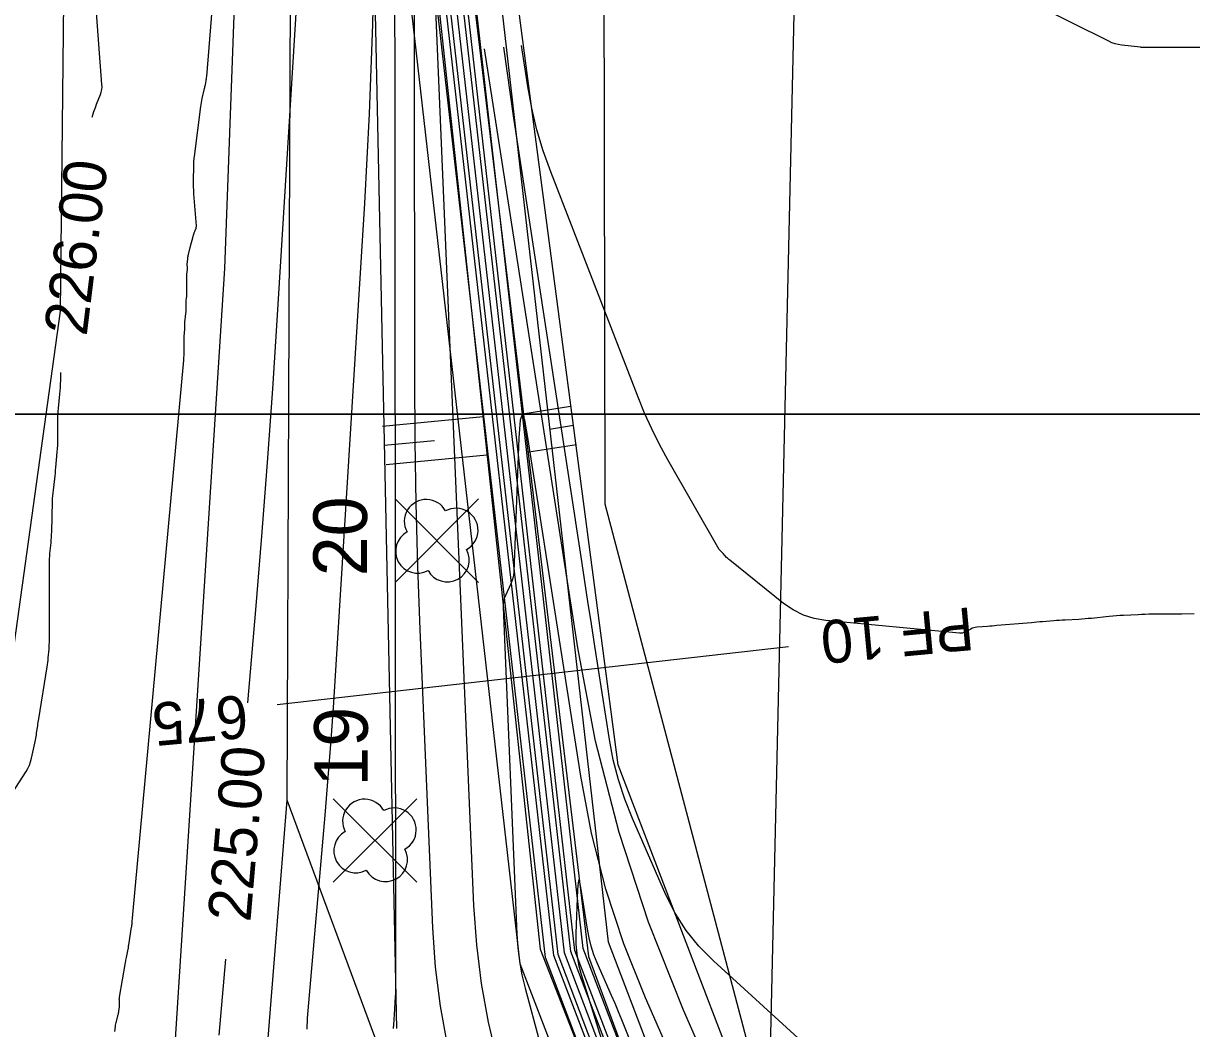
# Model space of a CAD drawing. Extents: x -534410 to -534262, y -1190162 to -1189584.
# Drawn here: x -534375.9 to -534348.66, y -1189913.8 to -1189890.36 of the extents above; entities that cross this region are included whole.
import ezdxf

# ---------------------------------------------------------------- set-up
doc = ezdxf.new("R2010")
doc.units = 0
for name, color, linetype in [('30', 7, 'Continuous'), ('31', 7, 'Continuous'), ('40', 7, 'Continuous'), ('_linie', 7, 'Continuous'), ('_N_osa', 7, 'Continuous'), ('_N_tenká', 7, 'Continuous'), ('_N_tenká_velmi', 7, 'Continuous'), ('_N_text', 7, 'Continuous'), ('_přístup', 7, 'Continuous'), ('_rámeček', 7, 'Continuous'), ('_tenka', 7, 'Continuous'), ('_velmi_tenka', 7, 'Continuous'), ('Default', 7, 'Continuous'), ('Hranice parcel', 7, 'Continuous')]:
    doc.layers.add(name, color=color, linetype=linetype)

msp = doc.modelspace()

# ---------------------------------------------------------------- linework, layer by layer
at = {"layer": '30'}
for points in [[(-534370.666, -1189906.203), (-534370.479, -1189904.035), (-534370.336, -1189902.317), (-534370.204, -1189900.599), (-534370.082, -1189898.88), (-534369.971, -1189897.16), (-534368.36, -1189871.02)], [(-534367.252, -1189877.424), (-534367.219, -1189912.738), (-534367.22, -1189912.819), (-534367.221, -1189912.899), (-534367.224, -1189912.979), (-534367.229, -1189913.06), (-534367.254, -1189913.474), (-534367.257, -1189913.507), (-534367.259, -1189913.541), (-534367.261, -1189913.575), (-534367.264, -1189913.609), (-534367.28, -1189913.791), (-534367.28, -1189913.8)], [(-534374.298, -1189892.543), (-534374.273, -1189892.468), (-534374.254, -1189892.41), (-534374.233, -1189892.353), (-534374.212, -1189892.296), (-534374.19, -1189892.24), (-534374.101, -1189892.014), (-534374.082, -1189891.956), (-534374.07, -1189891.898), (-534374.064, -1189891.839), (-534374.066, -1189891.779), (-534374.31, -1189888.535)], [(-534366.318, -1189889.293), (-534365.402, -1189910.932), (-534365.338, -1189911.844), (-534365.225, -1189912.749), (-534365.062, -1189913.646), (-534364.85, -1189914.535), (-534363.721, -1189918.76), (-534363.573, -1189919.304), (-534363.42, -1189919.847), (-534363.263, -1189920.389), (-534363.101, -1189920.929), (-534362.446, -1189923.087), (-534362.275, -1189923.625), (-534362.09, -1189924.157), (-534361.891, -1189924.684), (-534361.678, -1189925.205), (-534360.07, -1189929.007)], [(-534355.227, -1189925.422), (-534360.506, -1189913.368), (-534361.327, -1189911.316), (-534362.011, -1189909.224), (-534362.559, -1189907.092), (-534362.969, -1189904.92), (-534365.147, -1189890.948)], [(-534348.604, -1189904.127), (-534348.889, -1189904.131), (-534348.96, -1189904.132), (-534349.031, -1189904.132), (-534349.102, -1189904.133), (-534349.174, -1189904.134), (-534349.575, -1189904.136), (-534349.659, -1189904.137), (-534349.743, -1189904.139), (-534349.827, -1189904.142), (-534349.911, -1189904.146), (-534350.248, -1189904.163), (-534350.332, -1189904.168), (-534350.416, -1189904.174), (-534350.5, -1189904.181), (-534350.584, -1189904.189), (-534350.996, -1189904.231), (-534351.07, -1189904.238), (-534351.145, -1189904.245), (-534351.22, -1189904.25), (-534351.294, -1189904.255), (-534351.612, -1189904.273), (-534351.678, -1189904.276), (-534351.743, -1189904.281), (-534351.809, -1189904.285), (-534351.874, -1189904.29), (-534352.136, -1189904.311), (-534352.201, -1189904.316), (-534352.267, -1189904.321), (-534352.332, -1189904.326), (-534352.398, -1189904.332), (-534353.201, -1189904.401), (-534353.255, -1189904.406), (-534353.309, -1189904.41), (-534353.363, -1189904.415), (-534353.418, -1189904.419), (-534353.67, -1189904.439), (-534353.706, -1189904.444), (-534353.741, -1189904.452), (-534353.775, -1189904.464), (-534353.808, -1189904.48), (-534353.938, -1189904.549), (-534353.971, -1189904.564), (-534354.006, -1189904.574), (-534354.041, -1189904.578), (-534354.077, -1189904.577), (-534357.193, -1189904.28), (-534357.46, -1189904.235), (-534357.713, -1189904.154), (-534357.951, -1189904.036), (-534358.175, -1189903.882), (-534359.431, -1189902.875), (-534359.45, -1189902.859), (-534359.468, -1189902.843), (-534359.485, -1189902.826), (-534359.502, -1189902.809), (-534359.587, -1189902.718), (-534359.594, -1189902.711), (-534359.602, -1189902.703), (-534359.609, -1189902.696), (-534359.617, -1189902.688), (-534359.648, -1189902.659), (-534359.655, -1189902.652), (-534359.662, -1189902.644), (-534359.668, -1189902.635), (-534359.674, -1189902.626), (-534360.872, -1189900.532), (-534361.066, -1189900.177), (-534361.247, -1189899.815), (-534361.414, -1189899.447), (-534361.568, -1189899.072), (-534363.605, -1189893.818), (-534363.779, -1189893.331), (-534363.925, -1189892.836), (-534364.044, -1189892.335), (-534364.136, -1189891.826), (-534364.282, -1189890.875)], [(-534376.141, -1189908.282), (-534375.836, -1189907.806), (-534375.793, -1189907.732), (-534375.757, -1189907.655), (-534375.729, -1189907.575), (-534375.708, -1189907.493), (-534375.618, -1189907.069), (-534375.61, -1189907.028), (-534375.602, -1189906.987), (-534375.595, -1189906.945), (-534375.589, -1189906.904), (-534375.565, -1189906.737), (-534375.559, -1189906.696), (-534375.553, -1189906.654), (-534375.546, -1189906.613), (-534375.54, -1189906.571), (-534375.344, -1189905.363), (-534375.336, -1189905.311), (-534375.33, -1189905.26), (-534375.324, -1189905.208), (-534375.319, -1189905.156), (-534375.301, -1189904.948), (-534375.297, -1189904.896), (-534375.294, -1189904.844), (-534375.293, -1189904.792), (-534375.292, -1189904.74), (-534375.292, -1189902.971), (-534375.291, -1189902.908), (-534375.289, -1189902.845), (-534375.285, -1189902.782), (-534375.279, -1189902.719), (-534375.254, -1189902.468), (-534375.248, -1189902.405), (-534375.243, -1189902.342), (-534375.24, -1189902.279), (-534375.237, -1189902.216), (-534375.22, -1189901.504), (-534375.217, -1189901.438), (-534375.213, -1189901.372), (-534375.207, -1189901.306), (-534375.2, -1189901.24), (-534375.168, -1189900.976), (-534375.16, -1189900.91), (-534375.153, -1189900.844), (-534375.146, -1189900.778), (-534375.14, -1189900.712), (-534375.109, -1189900.359), (-534375.103, -1189900.277), (-534375.099, -1189900.196), (-534375.096, -1189900.115), (-534375.096, -1189900.034), (-534375.098, -1189899.651), (-534375.097, -1189899.57), (-534375.094, -1189899.489), (-534375.089, -1189899.408), (-534375.082, -1189899.328), (-534375.047, -1189899.006), (-534375.039, -1189898.925), (-534375.034, -1189898.844), (-534375.031, -1189898.763), (-534375.029, -1189898.683), (-534375.029, -1189898.498)], [(-534356.356, -1189927.44), (-534361.865, -1189913.788), (-534361.943, -1189913.596), (-534362.023, -1189913.405), (-534362.104, -1189913.215), (-534362.186, -1189913.025), (-534362.518, -1189912.267), (-534362.595, -1189912.075), (-534362.659, -1189911.88), (-534362.71, -1189911.681), (-534362.748, -1189911.478), (-534362.892, -1189910.553), (-534362.924, -1189910.387), (-534362.949, -1189910.332), (-534362.967, -1189910.389), (-534362.979, -1189910.558), (-534363.019, -1189911.581), (-534363.018, -1189911.825), (-534362.996, -1189912.067), (-534362.954, -1189912.305), (-534362.891, -1189912.541), (-534361.099, -1189918.283)], [(-534371.335, -1189913.953), (-534371.182, -1189912.181)]]:
    msp.add_lwpolyline(points, dxfattribs=at)
at = {"layer": '31'}
for points in [[(-534373.766, -1189913.868), (-534373.753, -1189913.749), (-534373.749, -1189913.719), (-534373.744, -1189913.69), (-534373.738, -1189913.66), (-534373.731, -1189913.631), (-534373.688, -1189913.472), (-534373.683, -1189913.451), (-534373.678, -1189913.431), (-534373.674, -1189913.41), (-534373.671, -1189913.388), (-534373.658, -1189913.3), (-534373.656, -1189913.281), (-534373.655, -1189913.261), (-534373.655, -1189913.242), (-534373.656, -1189913.223), (-534373.661, -1189913.145), (-534373.662, -1189913.125), (-534373.661, -1189913.106), (-534373.66, -1189913.086), (-534373.657, -1189913.067), (-534373.517, -1189912.257), (-534373.512, -1189912.229), (-534373.507, -1189912.2), (-534373.502, -1189912.172), (-534373.496, -1189912.144), (-534373.462, -1189911.982), (-534373.453, -1189911.94), (-534373.451, -1189911.928), (-534373.449, -1189911.916), (-534373.446, -1189911.881), (-534373.444, -1189911.865), (-534373.442, -1189911.849), (-534373.375, -1189911.434), (-534373.372, -1189911.417), (-534373.37, -1189911.4), (-534373.368, -1189911.383), (-534373.366, -1189911.365), (-534373.359, -1189911.279), (-534373.356, -1189911.244), (-534373.354, -1189911.227), (-534372.16, -1189898.211), (-534372.155, -1189898.153), (-534372.152, -1189898.096), (-534372.15, -1189898.038), (-534372.149, -1189897.98), (-534372.149, -1189897.663), (-534372.149, -1189897.649), (-534372.149, -1189897.634), (-534372.148, -1189897.62), (-534372.146, -1189897.605), (-534372.14, -1189897.547), (-534372.139, -1189897.533), (-534372.138, -1189897.518), (-534372.137, -1189897.504), (-534372.137, -1189897.489), (-534372.132, -1189897.325), (-534372.132, -1189897.31), (-534372.131, -1189897.294), (-534372.13, -1189897.279), (-534372.128, -1189897.264), (-534372.121, -1189897.203), (-534372.119, -1189897.188), (-534372.117, -1189897.173), (-534372.116, -1189897.157), (-534372.114, -1189897.142), (-534372.107, -1189897.061), (-534372.106, -1189897.042), (-534372.105, -1189897.023), (-534372.104, -1189897.004), (-534372.104, -1189896.986), (-534372.104, -1189896.897), (-534372.104, -1189896.879), (-534372.104, -1189896.86), (-534372.102, -1189896.841), (-534372.101, -1189896.823), (-534372.093, -1189896.748), (-534372.091, -1189896.73), (-534372.09, -1189896.711), (-534372.089, -1189896.692), (-534372.089, -1189896.674), (-534372.088, -1189896.562), (-534372.088, -1189896.513), (-534372.088, -1189896.432), (-534372.087, -1189896.383), (-534372.087, -1189896.291), (-534372.087, -1189896.27), (-534372.086, -1189896.25), (-534372.085, -1189896.229), (-534372.084, -1189896.208), (-534372.076, -1189896.097), (-534372.075, -1189896.083), (-534372.074, -1189896.07), (-534372.074, -1189896.056), (-534372.075, -1189896.043), (-534372.078, -1189895.989), (-534372.078, -1189895.976), (-534372.078, -1189895.963), (-534372.077, -1189895.949), (-534372.076, -1189895.936), (-534372.066, -1189895.832), (-534372.064, -1189895.81), (-534372.06, -1189895.788), (-534372.056, -1189895.767), (-534372.051, -1189895.746), (-534372.009, -1189895.585), (-534372.003, -1189895.563), (-534371.992, -1189895.519), (-534371.95, -1189895.356), (-534371.946, -1189895.341), (-534371.942, -1189895.327), (-534371.938, -1189895.312), (-534371.933, -1189895.298), (-534371.914, -1189895.24), (-534371.91, -1189895.226), (-534371.905, -1189895.213), (-534371.9, -1189895.2), (-534371.895, -1189895.187), (-534371.874, -1189895.135), (-534371.87, -1189895.122), (-534371.867, -1189895.108), (-534371.866, -1189895.095), (-534371.866, -1189895.081), (-534371.923, -1189894.332), (-534371.926, -1189894.282), (-534371.928, -1189894.233), (-534371.929, -1189894.183), (-534371.93, -1189894.133), (-534371.929, -1189893.908), (-534371.929, -1189893.87), (-534371.928, -1189893.833), (-534371.928, -1189893.796), (-534371.927, -1189893.758), (-534371.923, -1189893.608), (-534371.922, -1189893.571), (-534371.919, -1189893.534), (-534371.916, -1189893.496), (-534371.912, -1189893.459), (-534371.762, -1189892.294), (-534371.755, -1189892.247), (-534371.747, -1189892.2), (-534371.739, -1189892.154), (-534371.728, -1189892.108), (-534371.675, -1189891.878), (-534371.67, -1189891.854), (-534371.665, -1189891.831), (-534371.66, -1189891.808), (-534371.656, -1189891.785), (-534371.638, -1189891.692), (-534371.634, -1189891.669), (-534371.63, -1189891.645), (-534371.628, -1189891.622), (-534371.625, -1189891.598), (-534370.83, -1189881.739)], [(-534366.795, -1189883.114), (-534366.781, -1189898.62), (-534366.772, -1189900.088), (-534366.748, -1189901.556), (-534366.708, -1189903.024), (-534366.654, -1189904.491), (-534366.359, -1189911.452), (-534366.295, -1189912.368), (-534366.182, -1189913.277), (-534366.018, -1189914.179)], [(-534367.71, -1189888.284), (-534367.757, -1189890.373), (-534367.837, -1189892.462), (-534367.949, -1189894.549), (-534368.613, -1189905.317), (-534368.669, -1189906.194), (-534368.731, -1189907.07), (-534368.799, -1189907.946), (-534368.872, -1189908.822), (-534369.28, -1189913.554), (-534369.288, -1189913.812)], [(-534347.837, -1189890.92), (-534349.629, -1189890.921), (-534349.648, -1189890.921), (-534349.667, -1189890.921), (-534349.685, -1189890.92), (-534349.704, -1189890.92), (-534349.779, -1189890.918), (-534349.797, -1189890.918), (-534349.816, -1189890.916), (-534349.834, -1189890.915), (-534349.853, -1189890.913), (-534350.292, -1189890.863), (-534350.371, -1189890.85), (-534350.447, -1189890.831), (-534350.522, -1189890.806), (-534350.594, -1189890.773), (-534352.335, -1189889.91)], [(-534355.687, -1189915.981), (-534359.811, -1189912.222), (-534360.149, -1189911.88), (-534360.447, -1189911.509), (-534360.703, -1189911.109), (-534360.918, -1189910.679), (-534361.697, -1189908.901), (-534361.876, -1189908.452), (-534362.026, -1189907.994), (-534362.146, -1189907.528), (-534362.235, -1189907.053), (-534362.574, -1189904.883), (-534362.655, -1189904.362), (-534362.736, -1189903.84), (-534362.816, -1189903.318), (-534362.896, -1189902.797), (-534364.462, -1189892.567), (-534364.694, -1189890.91)], [(-534358.887, -1189918.812), (-534361.396, -1189913.081), (-534361.899, -1189911.826), (-534362.317, -1189910.547), (-534362.652, -1189909.243), (-534362.903, -1189907.914), (-534364.135, -1189900.011), (-534364.211, -1189899.607), (-534364.272, -1189899.474), (-534364.317, -1189899.613), (-534364.346, -1189900.023), (-534364.467, -1189903.148), (-534364.473, -1189903.221), (-534364.487, -1189903.293), (-534364.508, -1189903.362), (-534364.535, -1189903.43), (-534364.66, -1189903.699), (-534364.687, -1189903.767), (-534364.705, -1189903.837), (-534364.715, -1189903.909), (-534364.716, -1189903.982), (-534364.394, -1189911.593), (-534364.372, -1189911.913), (-534364.332, -1189912.23), (-534364.275, -1189912.545), (-534364.201, -1189912.857), (-534363.869, -1189914.099)]]:
    msp.add_lwpolyline(points, dxfattribs=at)
at = {"layer": '_linie'}
for points in [[(-534366.12, -1189620.81), (-534364.52, -1189627.2), (-534365.69, -1189653.8), (-534366.76, -1189684.81), (-534368.14, -1189748.73), (-534368.38, -1189779.14), (-534368.65, -1189820.64), (-534368.59, -1189847.58), (-534367.2, -1189913.8)], [(-534363.12, -1189621.02), (-534362.79, -1189621.58), (-534361.82, -1189627.79), (-534363.46, -1189653.55), (-534365.47, -1189684.77), (-534366.65, -1189748.83), (-534366.75, -1189779.47), (-534366.9, -1189820.47), (-534366.95, -1189846.72), (-534366.338, -1189888.804), (-534363.85, -1189911.95), (-534357.07, -1189929.19), (-534352.334, -1189940.856)], [(-534359.03, -1189621.26), (-534359.41, -1189621.83), (-534360.84, -1189627.76), (-534362.92, -1189653.56), (-534364.64, -1189685), (-534365.94, -1189748.9), (-534366.02, -1189779.52), (-534366.03, -1189820.5), (-534366.48, -1189846.73), (-534365.511, -1189888.873), (-534362.72, -1189912.12), (-534356.62, -1189928.64), (-534351.589, -1189940.594)]]:
    msp.add_lwpolyline(points, dxfattribs=at)
at = {"layer": '_N_osa'}
msp.add_lwpolyline([(-534351.95, -1189940.722), (-534356.845, -1189928.915), (-534363.285, -1189912.035), (-534365.925, -1189888.838), (-534366.715, -1189846.725), (-534366.465, -1189820.485), (-534366.385, -1189779.495), (-534366.295, -1189748.865), (-534365.055, -1189684.885), (-534363.19, -1189653.555), (-534361.333, -1189627.822)], dxfattribs=at)
at = {"layer": '_N_tenká'}
for points in [[(-534352.92, -1189941.124), (-534357.821, -1189929.303), (-534364.313, -1189912.285), (-534366.973, -1189888.908), (-534367.765, -1189846.73), (-534367.515, -1189820.479), (-534367.435, -1189779.492), (-534367.345, -1189748.853), (-534366.104, -1189684.844), (-534364.238, -1189653.486), (-534362.424, -1189628.352), (-534361.782, -1189627.792)], [(-534350.98, -1189940.319), (-534355.869, -1189928.527), (-534362.257, -1189911.785), (-534364.876, -1189888.769), (-534365.665, -1189846.72), (-534365.415, -1189820.491), (-534365.335, -1189779.498), (-534365.245, -1189748.877), (-534364.006, -1189684.926), (-534362.142, -1189653.624), (-534360.329, -1189628.488), (-534360.884, -1189627.851)]]:
    msp.add_lwpolyline(points, dxfattribs=at)
at = {"layer": '_N_tenká_velmi'}
for points in [[(-534352.366, -1189940.894), (-534357.263, -1189929.081), (-534363.726, -1189912.142), (-534366.374, -1189888.868), (-534367.165, -1189846.727), (-534366.915, -1189820.482), (-534366.835, -1189779.494), (-534366.745, -1189748.86), (-534365.505, -1189684.867), (-534363.639, -1189653.525), (-534361.782, -1189627.792)], [(-534352.181, -1189940.817), (-534357.077, -1189929.007), (-534363.53, -1189912.095), (-534366.174, -1189888.855), (-534366.965, -1189846.726), (-534366.715, -1189820.484), (-534366.635, -1189779.494), (-534366.545, -1189748.862), (-534365.305, -1189684.875), (-534363.439, -1189653.539), (-534361.583, -1189627.805)], [(-534352.089, -1189940.779), (-534356.984, -1189928.97), (-534363.432, -1189912.071), (-534366.074, -1189888.848), (-534366.865, -1189846.726), (-534366.615, -1189820.484), (-534366.535, -1189779.495), (-534366.445, -1189748.863), (-534365.205, -1189684.879), (-534363.34, -1189653.545), (-534361.483, -1189627.812)], [(-534351.812, -1189940.664), (-534356.706, -1189928.86), (-534363.138, -1189911.999), (-534365.775, -1189888.828), (-534366.565, -1189846.724), (-534366.315, -1189820.486), (-534366.235, -1189779.495), (-534366.145, -1189748.867), (-534364.905, -1189684.891), (-534363.04, -1189653.565), (-534361.184, -1189627.831)], [(-534351.719, -1189940.626), (-534356.613, -1189928.823), (-534363.04, -1189911.975), (-534365.675, -1189888.822), (-534366.465, -1189846.724), (-534366.215, -1189820.486), (-534366.135, -1189779.496), (-534366.045, -1189748.868), (-534364.805, -1189684.895), (-534362.941, -1189653.571), (-534361.084, -1189627.838)], [(-534351.534, -1189940.549), (-534356.427, -1189928.749), (-534362.844, -1189911.928), (-534365.475, -1189888.808), (-534366.265, -1189846.723), (-534366.015, -1189820.488), (-534365.935, -1189779.496), (-534365.845, -1189748.87), (-534364.605, -1189684.903), (-534362.741, -1189653.585), (-534360.884, -1189627.851)]]:
    msp.add_lwpolyline(points, dxfattribs=at)
at = {"layer": '_N_text'}
msp.add_lwpolyline([(-534358.059, -1189904.894), (-534369.982, -1189906.251)], dxfattribs=at)
at = {"layer": '_přístup'}
for p, q in [((-534365.287, -1189903.393), (-534367.233, -1189901.447)), ((-534367.233, -1189903.393), (-534365.287, -1189901.447)), ((-534366.727, -1189910.383), (-534368.673, -1189908.437)), ((-534368.673, -1189910.383), (-534366.727, -1189908.437))]:
    msp.add_line(p, q, dxfattribs=at)
for centre in [(-534366.26, -1189902.42), (-534367.7, -1189909.41)]:
    msp.add_circle(centre, 0.000512, dxfattribs=at)
for centre, start, end in [((-534366.505, -1189901.971), 28.6209, 208.6209), ((-534365.811, -1189902.175), 298.6209, 118.6209), ((-534366.709, -1189902.665), 118.6209, 298.6209), ((-534366.015, -1189902.869), 208.6209, 28.6209), ((-534367.945, -1189908.961), 28.6209, 208.6209), ((-534367.251, -1189909.165), 298.6209, 118.6209), ((-534368.149, -1189909.655), 118.6209, 298.6209), ((-534367.455, -1189909.859), 208.6209, 28.6209)]:
    msp.add_arc(centre, 0.512, start, end, dxfattribs=at)
at = {"layer": '_rámeček'}
for points in [[(-534410.126, -1189794.47), (-534261.626, -1189794.47), (-534261.626, -1189899.47), (-534410.126, -1189899.47)], [(-534410.126, -1189899.47), (-534261.626, -1189899.47), (-534261.626, -1190004.47), (-534410.126, -1190004.47)]]:
    msp.add_lwpolyline(points, close=True, dxfattribs=at)
at = {"layer": '_tenka'}
for points in [[(-534349.13, -1189939.73), (-534354.63, -1189926.96), (-534362.03, -1189907.65), (-534364.521, -1189888.74), (-534364.47, -1189846.64), (-534364.29, -1189820.63), (-534364.22, -1189780.69), (-534363.18, -1189749.38), (-534362.5, -1189685.39), (-534360.27, -1189651.6), (-534357.03, -1189627.34), (-534354.77, -1189620.37)], [(-534366.12, -1189620.81), (-534364.52, -1189627.2), (-534365.69, -1189653.8), (-534366.76, -1189684.81), (-534368.14, -1189748.73), (-534368.38, -1189779.14), (-534368.65, -1189820.64), (-534368.59, -1189847.58), (-534367.2, -1189913.8)], [(-534366.12, -1189620.81), (-534364.52, -1189627.2), (-534365.69, -1189653.8), (-534366.76, -1189684.81), (-534368.14, -1189748.73), (-534368.38, -1189779.14), (-534368.65, -1189820.64), (-534368.59, -1189847.58), (-534367.2, -1189913.8)], [(-534363.12, -1189621.02), (-534362.79, -1189621.58), (-534361.82, -1189627.79), (-534363.46, -1189653.55), (-534365.47, -1189684.77), (-534366.65, -1189748.83), (-534366.75, -1189779.47), (-534366.9, -1189820.47), (-534366.95, -1189846.72), (-534366.338, -1189888.804), (-534363.85, -1189911.95), (-534357.07, -1189929.19), (-534352.334, -1189940.856)], [(-534363.12, -1189621.02), (-534362.79, -1189621.58), (-534361.82, -1189627.79), (-534363.46, -1189653.55), (-534365.47, -1189684.77), (-534366.65, -1189748.83), (-534366.75, -1189779.47), (-534366.9, -1189820.47), (-534366.95, -1189846.72), (-534366.338, -1189888.804), (-534363.85, -1189911.95), (-534357.07, -1189929.19), (-534352.334, -1189940.856)], [(-534359.03, -1189621.26), (-534359.41, -1189621.83), (-534360.84, -1189627.76), (-534362.92, -1189653.56), (-534364.64, -1189685), (-534365.94, -1189748.9), (-534366.02, -1189779.52), (-534366.03, -1189820.5), (-534366.48, -1189846.73), (-534365.511, -1189888.873), (-534362.72, -1189912.12), (-534356.62, -1189928.64), (-534351.589, -1189940.594)], [(-534359.03, -1189621.26), (-534359.41, -1189621.83), (-534360.84, -1189627.76), (-534362.92, -1189653.56), (-534364.64, -1189685), (-534365.94, -1189748.9), (-534366.02, -1189779.52), (-534366.03, -1189820.5), (-534366.48, -1189846.73), (-534365.511, -1189888.873), (-534362.72, -1189912.12), (-534356.62, -1189928.64), (-534351.589, -1189940.594)], [(-534368.65, -1189626.81), (-534368.65, -1189626.81), (-534367.31, -1189654.04), (-534367.67, -1189685.23), (-534369.56, -1189748.93), (-534369.48, -1189778.6), (-534369.45, -1189820.62), (-534369.45, -1189847.87), (-534371.206, -1189896.071), (-534372.39, -1189914.47)]]:
    msp.add_lwpolyline(points, dxfattribs=at)
at = {"layer": '_velmi_tenka'}
for p, q in [((-534367.528, -1189899.748), (-534365.181, -1189899.524)), ((-534363.143, -1189899.292), (-534364.256, -1189899.469)), ((-534363.073, -1189899.736), (-534363.629, -1189899.825)), ((-534367.486, -1189900.196), (-534366.312, -1189900.084)), ((-534363.002, -1189900.181), (-534364.115, -1189900.357)), ((-534367.443, -1189900.644), (-534365.095, -1189900.42))]:
    msp.add_line(p, q, dxfattribs=at)
at = {"layer": 'Default'}
msp.add_lwpolyline([(-534349.13, -1189939.73), (-534354.63, -1189926.96), (-534362.03, -1189907.65), (-534364.521, -1189888.74), (-534364.47, -1189846.64), (-534364.29, -1189820.63), (-534364.22, -1189780.69), (-534363.18, -1189749.38), (-534362.5, -1189685.39), (-534360.27, -1189651.6), (-534357.03, -1189627.34), (-534354.77, -1189620.37)], dxfattribs=at)
at = {"layer": 'Hranice parcel'}
for p, q in [((-534369.75, -1189908.47), (-534369.38, -1189820.8)), ((-534362.34, -1189901.56), (-534358.53, -1189915.98)), ((-534370.62, -1189919.44), (-534369.75, -1189908.47)), ((-534366.49, -1189917.27), (-534369.75, -1189908.47))]:
    msp.add_line(p, q, dxfattribs=at)
for points in [[(-534359.48, -1189697.97), (-534362.6, -1189764.35), (-534362.34, -1189901.56)], [(-534359.48, -1189697.97), (-534360.42, -1189747.8), (-534359.17, -1189788.69), (-534356.86, -1189843.2), (-534358.53, -1189915.98)], [(-534373.61, -1189764.09), (-534375.04, -1189897.07), (-534384.28, -1189963.65)]]:
    msp.add_lwpolyline(points, dxfattribs=at)

# ---------------------------------------------------------------- texts
at = {"layer": '40'}
for s, rotation, p in [('226.00', 83.0143, (-534374.425, -1189897.667)), ('225.00', 85.0679, (-534370.607, -1189911.329))]:
    msp.add_text(s, height=1, rotation=rotation, dxfattribs=at).set_placement(p)
at = {"layer": '_N_text'}
for s, rotation, p in [('PF 10', 185.3129, (-534353.793, -1189903.969)), ('675', 185.2653, (-534370.709, -1189906.013))]:
    msp.add_text(s, height=1, rotation=rotation, dxfattribs=at).set_placement(p)
at = {"layer": '_přístup'}
for s, p in [('20', (-534367.888, -1189903.249)), ('19', (-534367.869, -1189908.154))]:
    msp.add_text(s, height=1.25, rotation=90, dxfattribs=at).set_placement(p)

doc.saveas('drawing.dxf')
